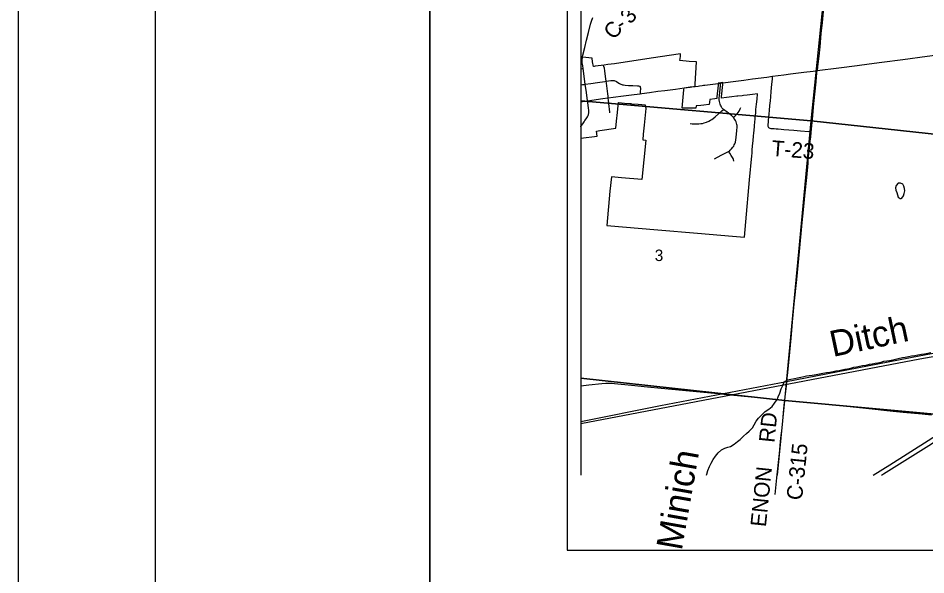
# Model space of a CAD drawing. Extents: x 0 to 34, y 0 to 22.
# Drawn here: x 0 to 3.306, y 17.411 to 19.439 of the extents above; entities that cross this region are included whole.
import ezdxf

# ---------------------------------------------------------------- set-up
doc = ezdxf.new("R2010")
doc.units = 0
for name, color, linetype in [('GM_X_City_Street', 7, 'Continuous'), ('GM_X_Corporation', 7, 'Continuous'), ('GM_X_County_Road', 7, 'Continuous'), ('GM_X_County_Road_Text', 7, 'Continuous'), ('GM_X_Minor_Lake', 7, 'Continuous'), ('GM_X_Minor_River', 7, 'Continuous'), ('GM_X_Minor_River_Text', 7, 'Continuous'), ('GM_X_Rail_Line', 7, 'Continuous'), ('GM_X_Section_Text', 7, 'Continuous'), ('GM_X_State_Route', 7, 'Continuous'), ('GM_X_Township_Road', 7, 'Continuous'), ('GM_X_Township_Road_Text', 7, 'Continuous'), ('GM_X_US_Route', 7, 'Continuous'), ('SH_Border', 7, 'Continuous'), ('SH_Cut_Line', 7, 'Continuous'), ('SH_Data', 7, 'Continuous')]:
    doc.layers.add(name, color=color, linetype=linetype)

msp = doc.modelspace()

# ---------------------------------------------------------------- linework, layer by layer
at = {"layer": 'GM_X_City_Street'}
for points in [[(2.0494, 19.2545), (2.055, 19.2551), (2.0577, 19.2553)], [(2.1493, 19.1481), (2.1487, 19.155), (2.1476, 19.1632), (2.1427, 19.2022), (2.1419, 19.2087), (2.1398, 19.2259), (2.1371, 19.2473), (2.1354, 19.2565), (2.1338, 19.2625), (2.1326, 19.2653)], [(2.0659, 19.1979), (2.0857, 19.2007), (2.1103, 19.2041), (2.1376, 19.2081), (2.1419, 19.2087), (2.1589, 19.2112), (2.165, 19.2119), (2.1681, 19.2119), (2.1711, 19.2114), (2.1741, 19.2105), (2.1769, 19.2093), (2.1797, 19.2078), (2.1849, 19.2044), (2.19, 19.201), (2.1927, 19.1995), (2.1956, 19.1982), (2.1985, 19.1971), (2.2014, 19.1963), (2.2045, 19.1956), (2.2106, 19.1947), (2.223, 19.1939), (2.2385, 19.1931), (2.2559, 19.1924), (2.26, 19.1922), (2.263, 19.1914), (2.2645, 19.1907), (2.2655, 19.1896), (2.2661, 19.188), (2.2664, 19.1867), (2.2665, 19.1839), (2.2654, 19.1685), (2.2655, 19.1648), (2.2655, 19.1634)], [(2.0494, 19.1958), (2.0556, 19.1966), (2.063, 19.1975), (2.0659, 19.1979)], [(2.554, 19.146), (2.554, 19.1475), (2.5548, 19.1575), (2.5579, 19.1923), (2.5584, 19.1999), (2.5586, 19.2023)], [(2.1559, 19.0937), (2.1556, 19.0966), (2.1515, 19.1283), (2.15, 19.1415), (2.1495, 19.1464), (2.1493, 19.1481)], [(2.5366, 18.9267), (2.5612, 18.939), (2.5804, 18.9487), (2.585, 18.9511), (2.588, 18.953), (2.5907, 18.9547), (2.5941, 18.9577), (2.5986, 18.9621), (2.6038, 18.9684), (2.6067, 18.9728), (2.6088, 18.9768), (2.6109, 18.9814), (2.6126, 18.9863), (2.6146, 18.9949), (2.6157, 19.0034), (2.6184, 19.0298), (2.619, 19.0421), (2.6188, 19.0472), (2.6181, 19.0516), (2.6169, 19.0563), (2.6153, 19.0605), (2.6131, 19.0654), (2.6111, 19.0691), (2.6075, 19.0746), (2.6054, 19.0774), (2.6035, 19.0796), (2.6013, 19.0819), (2.5989, 19.0839), (2.5939, 19.0878), (2.5811, 19.0968), (2.5738, 19.102), (2.5692, 19.1063), (2.5678, 19.1076), (2.5658, 19.1098), (2.5638, 19.1125), (2.5622, 19.115), (2.5604, 19.1182), (2.5589, 19.1216), (2.5573, 19.1255), (2.5558, 19.1298), (2.5546, 19.1349), (2.5541, 19.1415), (2.554, 19.146)], [(2.6054, 19.0774), (2.6111, 19.0821), (2.6149, 19.0856), (2.6192, 19.0901), (2.6231, 19.0948), (2.6266, 19.0998), (2.6281, 19.1025), (2.6305, 19.1082), (2.632, 19.1127)], [(2.4477, 19.0546), (2.4552, 19.0536), (2.4621, 19.0533), (2.4714, 19.0531), (2.479, 19.0534), (2.4871, 19.0543), (2.493, 19.0554), (2.499, 19.0571), (2.5078, 19.0602), (2.5164, 19.0638), (2.5219, 19.0667), (2.5272, 19.0699), (2.5322, 19.0736), (2.5394, 19.0795), (2.5633, 19.1005), (2.5676, 19.1047), (2.5692, 19.1063)], [(2.6071, 18.9174), (2.6056, 18.9232), (2.604, 18.9278), (2.6025, 18.9313), (2.6002, 18.935), (2.5977, 18.9389), (2.5922, 18.9469), (2.5891, 18.9512), (2.588, 18.953)]]:
    msp.add_lwpolyline(points, dxfattribs=at)
at = {"layer": 'GM_X_Corporation'}
msp.add_line((2.0494, 20.9578), (2.0494, 17.7739), dxfattribs=at)
for points in [[(2.0494, 20.1825), (2.0494, 19.1379), (2.8892, 19.065), (2.9941, 20.0934)], [(2.9941, 20.0934), (3.9531, 20.0055), (3.9103, 18.9545), (2.8892, 19.065)], [(2.0494, 19.2969), (2.0494, 19.001), (2.1093, 19.0092), (2.1069, 19.0274), (2.1186, 19.0291), (2.1775, 19.0377), (2.18, 19.0639), (2.1829, 19.0953), (2.1843, 19.1079), (2.1868, 19.1314), (2.1885, 19.1312), (2.2093, 19.1293), (2.2303, 19.1274), (2.2321, 19.1273), (2.2344, 19.1271), (2.2589, 19.1248), (2.2715, 19.1237), (2.2832, 19.1226), (2.2845, 19.1225), (2.286, 19.1091), (2.2803, 19.0486), (2.2772, 19.0156), (2.2753, 18.9954), (2.2866, 18.9944), (2.2714, 18.8508), (2.1973, 18.857), (2.1608, 18.8601), (2.1559, 18.8087), (2.1441, 18.6838), (2.3298, 18.6681), (2.4743, 18.6558), (2.6017, 18.645), (2.646, 18.6412), (2.6509, 18.6963), (2.6645, 18.8491), (2.6723, 18.9369), (2.6732, 18.9474), (2.6743, 18.9592), (2.6767, 18.9848), (2.6772, 18.9907), (2.6791, 19.0117), (2.6798, 19.0189), (2.6821, 19.0442), (2.6824, 19.0472), (2.6846, 19.0715), (2.6851, 19.0772), (2.6859, 19.086), (2.6866, 19.0929), (2.6877, 19.1054), (2.6897, 19.1252), (2.6915, 19.1441), (2.6934, 19.1629), (2.6746, 19.1607), (2.6558, 19.1585), (2.6426, 19.157), (2.6371, 19.1563), (2.6218, 19.1546), (2.6183, 19.1541), (2.5994, 19.152), (2.5806, 19.1498), (2.5622, 19.1476), (2.5622, 19.1477), (2.5623, 19.1478), (2.5623, 19.1479), (2.5623, 19.148), (2.5623, 19.1482), (2.5623, 19.1483), (2.5623, 19.1484), (2.5623, 19.1485), (2.5623, 19.1486), (2.5623, 19.1487), (2.5623, 19.1488), (2.5623, 19.1489), (2.5623, 19.149), (2.5623, 19.1491), (2.5623, 19.1492), (2.5623, 19.1494), (2.5623, 19.1495), (2.5623, 19.1496), (2.5623, 19.1497), (2.5623, 19.1498), (2.5623, 19.1499), (2.5623, 19.15), (2.5623, 19.1501), (2.5623, 19.1502), (2.5624, 19.1503), (2.5624, 19.1504), (2.5624, 19.1506), (2.5624, 19.1507), (2.5624, 19.1508), (2.5624, 19.1509), (2.5624, 19.151), (2.5624, 19.1511), (2.5624, 19.1512), (2.5624, 19.1513), (2.5624, 19.1514), (2.5624, 19.1515), (2.5624, 19.1516), (2.5625, 19.1517), (2.5625, 19.1519), (2.5625, 19.152), (2.5625, 19.1521), (2.5667, 19.1964), (2.5674, 19.2041), (2.5632, 19.2036), (2.5591, 19.203), (2.5533, 19.2023), (2.5526, 19.2022), (2.5503, 19.2019), (2.5496, 19.1941), (2.5457, 19.1525), (2.5457, 19.1524), (2.5456, 19.1522), (2.5456, 19.1521), (2.5456, 19.152), (2.5456, 19.1518), (2.5456, 19.1517), (2.5456, 19.1516), (2.5456, 19.1514), (2.5456, 19.1513), (2.5456, 19.1512), (2.5455, 19.151), (2.5455, 19.1509), (2.5455, 19.1508), (2.5455, 19.1506), (2.5455, 19.1505), (2.5455, 19.1504), (2.5455, 19.1502), (2.5455, 19.1501), (2.5455, 19.15), (2.5455, 19.1498), (2.5455, 19.1497), (2.5455, 19.1495), (2.5454, 19.1494), (2.5454, 19.1493), (2.5454, 19.1491), (2.5454, 19.149), (2.5454, 19.1489), (2.5454, 19.1487), (2.5454, 19.1486), (2.5454, 19.1485), (2.5454, 19.1483), (2.5454, 19.1482), (2.5454, 19.1481), (2.5454, 19.1479), (2.5454, 19.1478), (2.5454, 19.1477), (2.5454, 19.1475), (2.5454, 19.1474), (2.5454, 19.1473), (2.5454, 19.1471), (2.5454, 19.147), (2.5454, 19.1469), (2.5454, 19.1467), (2.5454, 19.1466), (2.5454, 19.1465), (2.5454, 19.1463), (2.5454, 19.1462), (2.5454, 19.1461), (2.5454, 19.1459), (2.5454, 19.1458), (2.5454, 19.1457), (2.5454, 19.1456), (2.5383, 19.1448), (2.519, 19.1426), (2.518, 19.1323), (2.5173, 19.1241), (2.5154, 19.1239), (2.4983, 19.122), (2.4866, 19.1207), (2.4698, 19.1188), (2.4692, 19.1108), (2.4404, 19.1106), (2.4366, 19.1105), (2.4186, 19.1104), (2.4253, 19.1775), (2.426, 19.1852), (2.4405, 19.1872), (2.4481, 19.1882), (2.4541, 19.189), (2.4659, 19.1906), (2.4663, 19.1983), (2.4708, 19.2792), (2.4449, 19.2813), (2.4108, 19.2841), (2.4123, 19.2996), (2.4133, 19.3091), (2.3054, 19.2928), (2.2508, 19.2846), (2.2269, 19.281), (2.1729, 19.2728), (2.1475, 19.2695), (2.1341, 19.2678), (2.1025, 19.2636), (2.0981, 19.263), (2.0953, 19.2627), (2.092, 19.28), (2.0905, 19.293), (2.0553, 19.2966)], [(2.0494, 19.1379), (2.0494, 18.1274), (2.7927, 18.046), (2.8892, 19.065)], [(2.8892, 19.065), (3.9103, 18.9545), (3.8182, 17.9517), (2.7927, 18.046)]]:
    msp.add_lwpolyline(points, close=True, dxfattribs=at)
for points in [[(2.7655, 17.7739), (2.7927, 18.046), (2.0494, 18.1274), (2.0494, 17.7739)], [(2.7655, 17.7739), (2.7927, 18.046), (3.8182, 17.9517), (3.798, 17.7739)]]:
    msp.add_lwpolyline(points, dxfattribs=at)
at = {"layer": 'GM_X_County_Road'}
msp.add_line((2.0659, 19.1979), (2.0577, 19.2553), dxfattribs=at)
for points in [[(2.9516, 19.6883), (2.9528, 19.6866), (2.9535, 19.6849), (2.954, 19.6821), (2.9541, 19.6791), (2.9534, 19.6699), (2.9499, 19.6389), (2.9418, 19.5586), (2.9324, 19.4628), (2.9284, 19.4226), (2.9243, 19.3827), (2.9197, 19.334), (2.9161, 19.3), (2.9134, 19.2724), (2.9106, 19.2475)], [(2.0556, 19.2962), (2.0559, 19.2983), (2.0571, 19.3043), (2.064, 19.3313), (2.0707, 19.3579), (2.0778, 19.3869), (2.0852, 19.4168), (2.0873, 19.4245), (2.0897, 19.4318), (2.0921, 19.4378), (2.0936, 19.441)], [(2.0577, 19.2553), (2.0564, 19.2645), (2.0549, 19.2757), (2.0546, 19.2815), (2.0545, 19.2858), (2.0548, 19.2899), (2.0552, 19.294), (2.0556, 19.2962)], [(2.8888, 19.0239), (2.8934, 19.071), (2.8988, 19.1277), (2.9065, 19.2067), (2.9083, 19.2242), (2.9098, 19.2398), (2.9106, 19.2475)], [(2.0736, 19.138), (2.0702, 19.1676), (2.0659, 19.1979)], [(2.0494, 19.0428), (2.05, 19.0438), (2.0525, 19.0476), (2.0566, 19.0535), (2.0613, 19.0606), (2.0647, 19.0655), (2.0688, 19.0715), (2.0736, 19.079), (2.0751, 19.0816), (2.0764, 19.0843), (2.0774, 19.0871), (2.0782, 19.09), (2.0786, 19.093), (2.0788, 19.096), (2.0785, 19.1022), (2.0773, 19.1114), (2.0748, 19.13), (2.0736, 19.138)], [(2.8784, 18.9205), (2.8808, 18.9444), (2.8855, 18.9907), (2.8871, 19.0055), (2.8888, 19.0239)], [(2.793, 18.0464), (2.7958, 18.0704), (2.7989, 18.0982), (2.8006, 18.1176), (2.8033, 18.1476), (2.8071, 18.1847), (2.8109, 18.2218), (2.8135, 18.2476), (2.8158, 18.2714), (2.8183, 18.3009), (2.8212, 18.3326), (2.8233, 18.3574), (2.8273, 18.3975), (2.8361, 18.4871), (2.846, 18.5891), (2.8564, 18.6942), (2.8611, 18.7405), (2.8648, 18.7776), (2.8671, 18.8023), (2.8724, 18.858), (2.8774, 18.9105), (2.8784, 18.9205)], [(2.0494, 18.0993), (2.0793, 18.1026), (2.1257, 18.1074), (2.1412, 18.1086), (2.1505, 18.109), (2.1599, 18.1089), (2.1724, 18.108), (2.2338, 18.1018), (2.2926, 18.0957), (2.342, 18.0906), (2.4844, 18.077), (2.5494, 18.0708), (2.5803, 18.0675), (2.6205, 18.0634), (2.6947, 18.0561), (2.7659, 18.0489), (2.7913, 18.0465), (2.793, 18.0464)], [(2.7577, 17.7037), (2.7638, 17.7642), (2.7731, 17.8527), (2.7776, 17.896), (2.7797, 17.9187), (2.7813, 17.9358), (2.7852, 17.9718), (2.7895, 18.0148), (2.7921, 18.0395), (2.793, 18.0464)], [(2.793, 18.0464), (2.8243, 18.0434), (2.8736, 18.039), (2.9383, 18.033), (2.9786, 18.0293), (3.031, 18.0239), (3.1224, 18.0137), (3.1533, 18.0107), (3.1873, 18.0074), (3.2244, 18.0038), (3.2928, 17.9975), (3.3265, 17.994)]]:
    msp.add_lwpolyline(points, dxfattribs=at)
at = {"layer": 'GM_X_Minor_Lake'}
for points in [[(3.2097, 18.8373), (3.2056, 18.8375), (3.1983, 18.8293), (3.1959, 18.8206), (3.1977, 18.8118), (3.201, 18.803), (3.2032, 18.7954), (3.2054, 18.7867), (3.2129, 18.7812), (3.2168, 18.782)], [(3.2168, 18.782), (3.2194, 18.7827), (3.2248, 18.791), (3.2279, 18.7997), (3.2303, 18.8095), (3.2293, 18.8183), (3.226, 18.8263), (3.2223, 18.8339), (3.2147, 18.837), (3.2097, 18.8373)]]:
    msp.add_lwpolyline(points, dxfattribs=at)
at = {"layer": 'GM_X_Minor_River'}
for points in [[(3.2308, 18.2038), (3.2438, 18.2063), (3.2548, 18.2084), (3.2662, 18.2102), (3.2776, 18.212), (3.291, 18.2141), (3.3016, 18.2162), (3.3245, 18.2205)], [(2.5072, 17.7739), (2.5084, 17.7779), (2.5127, 17.7911), (2.5182, 17.8055), (2.5241, 17.8179), (2.5314, 17.8311), (2.5399, 17.8424), (2.55, 17.8556), (2.5615, 17.8657), (2.5741, 17.8716), (2.5848, 17.876), (2.5943, 17.8786), (2.6077, 17.8868), (2.62, 17.8965), (2.63, 17.904), (2.6427, 17.916), (2.6534, 17.9257), (2.6634, 17.9335), (2.6753, 17.9463), (2.6808, 17.9576), (2.6881, 17.9704), (2.6966, 17.981), (2.7216, 18.0053), (2.7343, 18.0139), (2.7465, 18.0233), (2.7547, 18.0365), (2.7647, 18.0496), (2.7686, 18.0594), (2.7745, 18.073), (2.7796, 18.0886), (2.7851, 18.1006), (2.7906, 18.1135), (2.8025, 18.1209), (2.815, 18.1231), (2.8276, 18.1259), (2.8386, 18.1281), (2.8512, 18.131), (2.8619, 18.1335), (2.8718, 18.1356), (2.8817, 18.137), (2.8927, 18.1384), (2.9064, 18.1405), (2.9186, 18.1427), (2.9308, 18.1452), (2.9441, 18.1477), (2.9563, 18.1494), (2.9685, 18.1516), (2.9787, 18.1533), (2.9909, 18.1555), (3.0008, 18.158), (3.0111, 18.1594), (3.021, 18.1615), (3.0336, 18.164), (3.0442, 18.1666), (3.0538, 18.1687), (3.0652, 18.1713), (3.0758, 18.1734), (3.0888, 18.1748), (3.1013, 18.1777), (3.1112, 18.1794), (3.1219, 18.182), (3.1314, 18.1834), (3.1432, 18.1859), (3.1535, 18.1888), (3.1646, 18.1902), (3.1741, 18.1916), (3.1863, 18.1933), (3.1962, 18.1959), (3.2057, 18.1984), (3.2209, 18.202), (3.2308, 18.2038)]]:
    msp.add_lwpolyline(points, dxfattribs=at)
at = {"layer": 'GM_X_Rail_Line'}
for points in [[(3.8692, 18.3151), (3.7762, 18.3006), (3.2823, 18.2072), (2.7983, 18.1135), (2.3397, 18.0267), (2.0494, 17.9677)], [(2.0494, 17.9624), (3.2848, 18.1978), (3.8715, 18.3004), (3.925, 18.3113)]]:
    msp.add_lwpolyline(points, dxfattribs=at)
at = {"layer": 'GM_X_State_Route'}
for points in [[(3.1146, 17.7739), (3.1751, 17.8116), (3.3152, 17.9005), (3.3625, 17.9303), (3.4781, 18.0033), (3.6648, 18.1207), (3.7226, 18.1571), (3.7777, 18.192), (3.8671, 18.2482), (3.9196, 18.2814), (3.9722, 18.3146), (4.0195, 18.3442), (4.1115, 18.4022), (4.143, 18.422), (4.1615, 18.4336), (4.1806, 18.4456), (4.2009, 18.4584), (4.2299, 18.4766), (4.3463, 18.5502), (4.374, 18.5677)], [(3.1448, 17.7739), (3.1523, 17.7785), (3.2294, 17.8269), (3.3171, 17.8823), (3.4064, 17.9385), (3.4967, 17.9957), (3.5584, 18.0343), (3.6406, 18.0865), (3.731, 18.1434), (3.8287, 18.2051), (3.9189, 18.2619), (4.0139, 18.3216), (4.1002, 18.3763), (4.154, 18.41)]]:
    msp.add_lwpolyline(points, dxfattribs=at)
at = {"layer": 'GM_X_Township_Road'}
msp.add_lwpolyline([(2.8888, 19.0239), (2.8866, 19.0241), (2.8806, 19.0247), (2.8504, 19.0274), (2.8251, 19.0295), (2.7893, 19.0324), (2.78, 19.0333), (2.7685, 19.0342), (2.761, 19.0347), (2.7534, 19.035), (2.747, 19.0353), (2.7428, 19.0358), (2.7396, 19.0365), (2.7367, 19.0375), (2.7343, 19.0392), (2.7327, 19.0414), (2.7319, 19.0441), (2.7315, 19.0471), (2.7317, 19.0511), (2.7327, 19.0594), (2.7336, 19.068), (2.7347, 19.077), (2.7362, 19.0899), (2.7374, 19.1026), (2.7387, 19.1209), (2.7402, 19.1373), (2.7415, 19.1516), (2.743, 19.1712), (2.7455, 19.1983), (2.7477, 19.2162), (2.7479, 19.2201), (2.7479, 19.2233), (2.7478, 19.2256), (2.7477, 19.2268)], dxfattribs=at)
at = {"layer": 'GM_X_US_Route'}
msp.add_line((2.4661, 19.19), (2.4773, 19.1915), dxfattribs=at)
for points in [[(2.9106, 19.2475), (2.9889, 19.2574), (3.0566, 19.2663), (3.0997, 19.2721), (3.1459, 19.2781), (3.2229, 19.2881), (3.3115, 19.2997), (3.3577, 19.3057), (3.442, 19.3169), (3.4963, 19.3239), (3.5456, 19.3304), (3.6376, 19.3426), (3.641, 19.343), (3.6841, 19.3488), (3.7735, 19.3605), (3.8474, 19.3703), (3.8774, 19.3743), (3.8997, 19.3773), (3.9273, 19.3811)], [(2.4971, 19.1941), (2.5011, 19.1946), (2.5505, 19.2012), (2.5586, 19.2023), (2.5676, 19.2034), (2.5953, 19.207), (2.6433, 19.2132), (2.6751, 19.2175), (2.7274, 19.2242), (2.7477, 19.2268), (2.7888, 19.232), (2.8134, 19.2354), (2.8626, 19.2416), (2.8966, 19.2457), (2.9106, 19.2475)], [(2.2655, 19.1634), (2.2718, 19.1642), (2.2996, 19.1679), (2.3303, 19.1721), (2.3559, 19.1752), (2.3944, 19.1802), (2.4263, 19.1847), (2.4485, 19.1876), (2.4507, 19.1879), (2.4661, 19.19)], [(2.4773, 19.1915), (2.4814, 19.192), (2.492, 19.1934), (2.4971, 19.1941)], [(2.0736, 19.138), (2.0902, 19.1403), (2.1302, 19.1456), (2.1485, 19.148), (2.1493, 19.1481), (2.167, 19.1505), (2.2047, 19.1554), (2.2441, 19.1607), (2.2655, 19.1634)], [(2.0494, 19.1347), (2.0558, 19.1356), (2.0736, 19.138)]]:
    msp.add_lwpolyline(points, dxfattribs=at)
at = {"layer": 'SH_Border'}
for points in [[(0.5, 21.5), (1.5, 21.5), (1.5, 0.5), (0.5, 0.5)], [(1.5, 21.5), (33.5, 21.5), (33.5, 0.5), (1.5, 0.5)]]:
    msp.add_lwpolyline(points, close=True, dxfattribs=at)
at = {"layer": 'SH_Cut_Line'}
msp.add_lwpolyline([(0, 0), (34, 0), (34, 22), (0, 22)], close=True, dxfattribs=at)
at = {"layer": 'SH_Data'}
for p, q in [((2, 21), (2, 17.5)), ((2, 17.5), (9, 17.5))]:
    msp.add_line(p, q, dxfattribs=at)

# ---------------------------------------------------------------- texts
at = {"layer": 'GM_X_County_Road_Text'}
for s, height, rotation, p in [('3', 0.0568, 48.968, (2.2305, 19.4142)), ('C', 0.0568, 50.0765, (2.1707, 19.3572)), ('-', 0.0568, 32.2751, (2.1971, 19.39)), ('RD', 0.05682, 84.1432, (2.7546, 17.8904)), ('C-315', 0.05682, 84.0018, (2.855, 17.6806)), ('ENON', 0.05682, 84.1186, (2.7237, 17.5835))]:
    msp.add_text(s, height=height, rotation=rotation, dxfattribs=at).set_placement(p)
at = {"layer": 'GM_X_Minor_River_Text'}
for s, height, rotation, p in [('Ditch', 0.09469, 11.9823, (2.9676, 18.204)), ('Minich', 0.09466, 79.9998, (2.4172, 17.4965))]:
    msp.add_text(s, height=height, rotation=rotation, dxfattribs=at).set_placement(p)
at = {"layer": 'GM_X_Section_Text'}
msp.add_text('3', height=0.0419, rotation=0, dxfattribs=at).set_placement((2.3189, 18.5537))
at = {"layer": 'GM_X_Township_Road_Text'}
msp.add_text('T-23', height=0.05682, rotation=355.4669, dxfattribs=at).set_placement((2.7426, 18.9374))

doc.saveas('drawing.dxf')
